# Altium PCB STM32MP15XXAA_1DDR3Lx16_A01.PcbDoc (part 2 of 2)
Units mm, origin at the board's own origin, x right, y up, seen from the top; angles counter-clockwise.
Board outline 86 x 120 mm, 6 copper layers (Top Layer, Signal Layer 1, Signal Layer 2, Signal Layer 3, Signal Layer 4, Bottom Layer), stack 1.556 mm thick; 100 components, 91 nets, 936 pads, 390 vias.
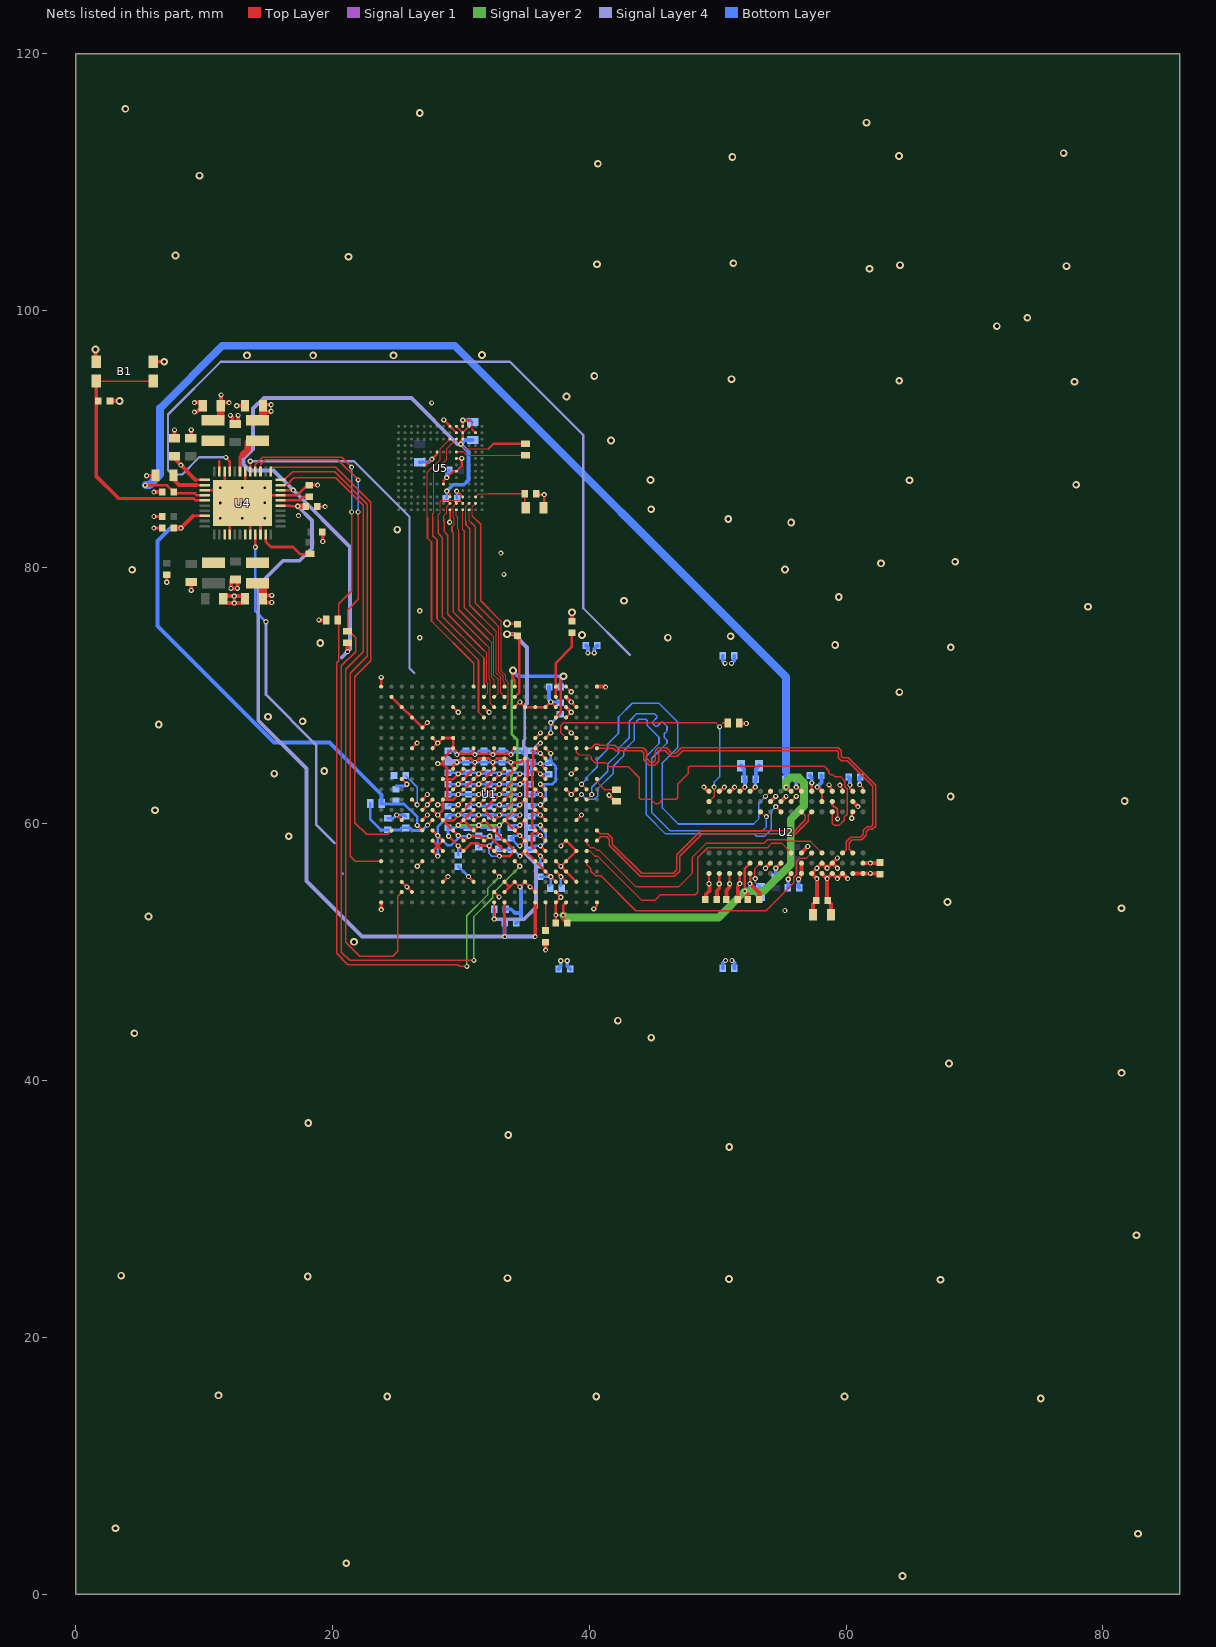
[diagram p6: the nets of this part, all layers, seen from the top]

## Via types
v1: diameter 0.4, hole 0.2, Top Layer to Bottom Layer, tented both sides, 295 vias
v2: diameter 0.6, hole 0.3, Top Layer to Bottom Layer, tented both sides, 93 vias
v3: diameter 0.4, hole 0.2, Top Layer to Signal Layer 1, tented top, 2 vias

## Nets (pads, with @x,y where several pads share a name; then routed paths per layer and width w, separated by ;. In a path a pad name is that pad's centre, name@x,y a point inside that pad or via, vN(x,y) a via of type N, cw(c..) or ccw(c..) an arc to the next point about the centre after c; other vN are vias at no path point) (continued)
DDR_DQ14: U1.U21 U2.H7 | length 21.3
  Top Layer w0.12: U1.U21@39.8,57.9 40.055,57.9 40.45,57.505 40.648,57.505 44.078,54.075 45.135,54.075 45.55,54.49 48.265,54.49 48.455,54.68 48.455,57.385 49.225,58.155 53.88,58.155 54.235,58.51 54.97,58.51 U2.H7@55.73,57.75
DDR_DQ15: U1.V21 U2.F7 | length 22.1
  Top Layer w0.12: U1.V21@39.8,57.1 39.8,56.85 40.12,56.53 40.12,56.327 40.467,55.98 40.893,55.98 43.628,53.245 53.767,53.245 55.935,55.413 55.935,55.846 56.145,56.056 56.145,57.074 56.421,57.35 56.93,57.35 U2.F7@57.33,57.75
DDR_DQM0: U1.G20 U2.D3 | length 31.9
  Top Layer w0.09: 39.184,65.405 39.98,65.405 40.16,65.225
  Top Layer w0.12: U1.G20@39,65.9 39,65.589 39.184,65.405 ; 40.16,65.225 40.16,65.055 40.435,64.78 41.275,64.78 41.585,64.47 43.036,64.47 43.895,63.611 43.895,62.015 43.993,61.917 44.822,61.917 45.154,61.584 45.391,61.584 45.726,61.92 46.77,61.92 46.89,62.04 46.89,63.106 47.715,63.931 47.715,64.41 47.785,64.48 58.336,64.48 58.662,64.154 58.662,63.963 58.805,63.82 58.996,63.82 59.125,63.691 59.572,63.691 59.892,63.372 59.892,62.939 60.09,62.741 60.09,60.765 59.86,60.535 59.86,60.289 59.458,59.888 59.09,59.888 58.93,60.048 U2.D3@58.93,60.95
DDR_DQM1: U1.T21 U2.E7 | length 22.6
  Top Layer w0.12: U1.T21@39.8,58.7 39.8,58.485 40.145,58.14 40.402,58.14 40.597,57.945 40.794,57.945 43.644,55.095 46.962,55.095 48.04,56.174 48.04,57.42 49.135,58.515 53.625,58.515 53.89,58.78 55.325,58.78 55.46,58.645 57.235,58.645 U2.E7@58.13,57.75
DDR_DQS0_N: U1.G21 U2.B7 | length 33.1
  Top Layer w0.1: U1.G21@39.8,65.9 40.162,65.9 40.472,66.21 40.728,66.21 40.808,66.13 41.98,66.13 42.175,65.935 44.19,65.935 44.469,65.656 44.469,65.109 44.758,64.82 45.015,64.82 45.15,64.955 45.15,65.695 45.39,65.935 46.02,65.935 46.435,65.52 46.753,65.52 47.178,65.945 59.39,65.945 59.62,65.715 59.62,65.268 59.731,65.156 60.179,65.156 62.315,63.02 62.315,59.84 62.05,59.575 61.755,59.575 61.593,59.412 61.593,59.117 61.23,58.755 60.47,58.755 60.25,58.535 60.25,58.03 U2.B7@60.53,57.75
DDR_DQS0_P: U1.G22 U2.C7 | length 31.8
  Top Layer w0.1: U1.G22@40.6,65.9 41.751,65.9 ; 41.768,65.9 41.885,65.9 42.08,65.705 44.095,65.705 44.239,65.561 44.239,65.013 44.662,64.59 45.11,64.59 45.405,64.885 45.405,65.575 45.535,65.705 45.925,65.705 46.34,65.29 46.848,65.29 47.273,65.715 59.295,65.715 59.39,65.62 59.39,65.173 59.636,64.926 60.084,64.926 62.085,62.925 62.085,59.935 61.955,59.805 61.66,59.805 61.363,59.508 61.363,59.213 61.135,58.985 60.375,58.985 60.02,58.63 60.02,57.99 U2.C7@59.73,57.7
DDR_DQS1_N: U1.R22 U2.G3 | length 21.1
  Top Layer w0.1: U1.R22@40.6,59.5 40.875,59.225 41.463,59.225 41.795,58.893 41.795,58.429 44.079,56.145 46.527,56.145 46.808,56.426 46.808,57.594 48.7,59.485 56.01,59.485 56.84,60.315 56.84,60.64 U2.G3@56.53,60.95
DDR_DQS1_P: U1.T22 U2.F3 | length 21.4
  Top Layer w0.1: U1.T22@40.6,58.7 40.895,58.995 41.367,58.995 41.565,58.797 41.565,58.334 43.984,55.915 46.622,55.915 47.038,56.331 47.038,57.498 48.795,59.255 56.105,59.255 57.07,60.22 57.07,60.69 U2.F3@57.33,60.95
DDR_ODT: U1.L21 U2.K1 | length 30.7
  Top Layer w0.12: v1(39.4,63.1) U1.L21@39.8,62.7 ; v1(53.73,62.15) U2.K1@54.13,62.55
  Bottom Layer w0.12: v1@39.512,63.1 v1(39.4,63.1) 39.79,63.49 39.79,63.62 40.62,64.45 40.62,65.012 41.45,65.842 41.45,66.229 42.28,67.059 42.28,68.341 43.349,69.41 45.429,69.41 46.89,67.949 46.89,65.959 45.7,64.769 45.7,61.239 46.939,60 52.794,60 53.215,60.421 53.215,61.635 v1(53.73,62.15)
DDR_RASN: U1.M20 U2.J3 | length 31.3
  Top Layer w0.12: U1.M20@39,61.9 v1(39.4,62.3) ; v1(54.53,61.35) U2.J3@54.93,60.95
  Bottom Layer w0.12: v1(39.4,62.3) 39.775,61.925 40.41,61.925 40.65,62.165 40.65,62.719 41.865,63.934 41.865,64.496 42.695,65.326 42.695,65.714 43.525,66.544 43.525,67.825 43.865,68.165 44.4,68.165 44.52,68.045 44.52,67.668 45.435,66.753 45.435,66.265 44.455,65.285 44.455,60.723 45.949,59.229 52.857,59.229 53.044,59.043 53.659,59.043 54.165,59.548 54.165,60.985 v1(54.53,61.35)
DDR_RESETN: R29.2 U1.F19 U2.T2 | length 20.6
  Top Layer w0.12: U1.F19@38.2,66.7 37.799,67.101 37.799,67.694 37.975,67.87 49.88,67.87 v1@50.155,67.595 ; U2.T2@49.33,61.75 49.73,62.15 v1(49.73,62.875) ; v1(50.155,67.565) v1@50.155,67.595 ; R29.2@50.775,67.87 50.42,67.87 50.155,67.605 v1@50.155,67.595
  Bottom Layer w0.12: v1(49.73,62.875) 49.755,62.9 49.755,63.275 50.155,63.675 v1(50.155,67.565)
DDR_WEN: U1.M21 U2.L3 | length 30.4
  Top Layer w0.12: U1.M21@39.8,61.9 v1(40.2,62.3) ; U2.L3@53.33,60.95 v1@53.655,60.625
  Bottom Layer w0.12: v1(40.2,62.3) 40.2,62.856 41.45,64.106 41.45,64.668 42.28,65.498 42.28,65.886 43.11,66.716 43.11,67.997 43.693,68.58 45.085,68.58 45.255,68.41 45.255,68.27 44.935,67.95 44.935,67.84 45.17,67.605 45.305,67.605 45.625,67.925 45.738,67.925 46.06,67.603 46.06,67.245 45.85,67.035 45.85,66.735 46.06,66.525 46.06,66.303 44.87,65.113 44.87,60.895 46.276,59.489 53.519,59.489 53.8,59.77 v1(53.8,60.57)
eMMC_SDIO2_D0: U1.A13 U5.A3 | length 14.9
  Top Layer w0.09: U5.A3@30.65,84.475 30.65,83.634 30.825,83.459 ; 32.739,75.595 32.96,75.374 32.96,71.824 33.295,71.489 33.295,71.14 33.4,71.035 U1.A13@33.4,70.7
  Top Layer w0.13: 30.825,83.459 31.115,83.169 31.115,77.219 32.739,75.595
eMMC_SDIO2_D1: U1.B12 U5.A4 | length 15.9
  Top Layer w0.09: U5.A4@30.15,84.475 30.15,82.932 30.265,82.817 ; 32.356,74.776 32.58,74.552 32.58,71.595 32.905,71.27 32.905,70.185 U1.B12@32.62,69.9
  Top Layer w0.13: 30.265,82.817 30.265,76.867 32.356,74.776 ; U1.B12@32.6,69.965 U1.B12@32.6,69.9 U1.B12@32.62,69.9
eMMC_SDIO2_D2: U1.A12 U5.A5 | length 15
  Top Layer w0.09: U5.A5@29.65,84.475 29.65,84.005 29.775,83.88 29.775,83.005 29.84,82.94 29.84,82.669 ; 32.145,74.385 32.39,74.141 32.39,71.44 32.6,71.23 U1.A12@32.6,70.7
  Top Layer w0.13: 29.84,82.669 29.84,76.691 32.145,74.385
eMMC_SDIO2_D3: U1.C13 U5.B2 | length 17.3
  Top Layer w0.09: 30.9,83.985 30.9,84.725 U5.B2@31.15,84.975 ; 33.015,75.92 33.15,75.785 33.15,71.902 33.485,71.567 33.485,71.219 33.71,70.994 33.71,69.41 U1.C13@33.4,69.1
  Top Layer w0.13: 30.9,83.985 31.54,83.345 31.54,77.395 33.015,75.92
eMMC_SDIO2_D4: U1.B13 U5.B3 | length 16.4
  Top Layer w0.09: 30.4,83.55 30.4,84.725 U5.B3@30.65,84.975 ; 32.584,75.149 32.77,74.963 32.77,71.745 33.095,71.42 33.095,70.205 U1.B13@33.4,69.9
  Top Layer w0.13: 30.4,83.55 30.4,83.283 30.69,82.993 30.69,77.043 32.584,75.149
eMMC_SDIO2_D5: U1.A11 U5.B4 | length 17.9
  Top Layer w0.09: 28.25,83.685 28.25,84.105 28.4,84.255 28.4,85.125 28.5,85.225 29.9,85.225 U5.B4@30.15,84.975
  Top Layer w0.13: 28.25,83.685 28.25,82.633 28.565,82.318 28.565,76.163 31.8,72.928 U1.A11@31.8,70.7
eMMC_SDIO2_D6: U1.C12 U5.B5 | length 17.5
  Top Layer w0.09: 29.31,83.155 29.5,83.345 29.5,83.785 29.4,83.885 29.4,84.725 U5.B5@29.65,84.975 ; 31.96,73.97 32.2,73.73 32.2,71.295 32.295,71.2 32.295,69.405 U1.C12@32.6,69.1
  Top Layer w0.13: 29.31,83.155 29.31,82.775 29.415,82.67 29.415,76.515 31.96,73.97
eMMC_SDIO2_D7: U1.B11 U5.B6 | length 16.8
  Top Layer w0.09: 28.675,83.861 28.675,84.01 28.9,84.235 28.9,84.725 U5.B6@29.15,84.975 ; 31.794,73.534 32.01,73.319 32.01,71.055 32.105,70.96 32.105,70.205 U1.B11@31.8,69.9
  Top Layer w0.13: 28.675,83.861 28.675,83.568 28.703,83.54 28.703,82.781 28.99,82.494 28.99,76.339 31.794,73.534
GND: B1.1 B1.2 C13.1 C14.1 C15.1 C16.1 C17.1 C18.1 C19.1 C20.1 C21.1 C22.2 C23.1 C24.1 C25.1 C26.1 C27.1 C28.1 C29.1 C30.1 C31.1 C32.1 C33.1 C34.1 C35.1 C36.1 C37.1 C38.1 C39.1 C40.1 C41.1 C42.1 C43.1 C44.1 C45.1 C46.1 C47.1 C48.1 C49.1 C50.1 C51.2 C52.1 C53.1 C54.1 C55.1 C56.1 C57.1 C58.1 C59.1 C60.1 C61.1 C62.1 C63.1 C64.1 C65.1 C66.1 C67.1 C68.1 C69.1 C70.1 C71.1 C72.1 C73.1 C74.1 C75.1 C76.1 C79.1 C80.1 C81.1 C82.1 C83.1 C84.1 C85.1 C86.1 C87.1 C90.1 C91.1 C92.1 C93.1 C94.1 C95.1 C96.1 C97.1 R26.1 R27.2 R29.1 R30.1 U1.A1 U1.A19 U1.A22 U1.AA4 U1.AA12 U1.AA13 U1.AA16 U1.AA18 U1.AB1 U1.AB18 U1.AB22 U1.B2 U1.B19 U1.C3 U1.C8 U1.C11 U1.C14 U1.C15 U1.C16 U1.C17 U1.C18 U1.C19 U1.C20 U1.D4 U1.D19 U1.E5 U1.E19 U1.F6 U1.F7 U1.F8 U1.F16 U1.F20 U1.G4 U1.G6 U1.G8 U1.G10 U1.G12 U1.G14 U1.G17 U1.H7 U1.J9 U1.J11 U1.J13 U1.J17 U1.J20 U1.K3 U1.K7 U1.K10 U1.K12 U1.K14 U1.L9 U1.L11 U1.L13 U1.L17 U1.L19 U1.L20 U1.M5 U1.M7 U1.M10 U1.M12 U1.M14 U1.N6 U1.N9 U1.N11 U1.N13 U1.N17 U1.P3 U1.P5 U1.P7 U1.P10 U1.P12 U1.P14 U1.P20 U1.R6 U1.R8 U1.R17 U1.T6 U1.T7 U1.T9 U1.T11 U1.T19 U1.U6 U1.U7 U1.U13 U1.U15 U1.U17 U1.U20 U1.V5 U1.V16 U1.V18 U1.V19 U1.W17 U1.W19 U1.Y3 U1.Y7 U1.Y10 U1.Y13 U1.Y14 U1.Y15 U1.Y18 U1.Y20 U2.A9 U2.B1 U2.B3 U2.B9 U2.D1 U2.D8 U2.E1 U2.E2 U2.E8 U2.F9 U2.G1 U2.G8 U2.G9 U2.J2 U2.J8 U2.M1 U2.M9 U2.P1 U2.P9 U2.T1 U2.T9 U4.6 U4.10 U4.15 U4.26 U4.30 U4.32 U4.41 U4.ep U5.A6 U5.C4 U5.E7 U5.G5 U5.H10 U5.J5 U5.K8 U5.N2 U5.N5 U5.P4 U5.P6 | length 247.4
  Top Layer w0.09: 30.675,91.45 30.9,91.225 30.9,90.725
  Top Layer w0.12: U1.E19@38.2,67.5 v1(38.6,67.1) U1.F20@39,66.7 ; U1.A19@38.2,70.7 v1(38.6,70.3) ; U2.M1@52.53,62.5 U2.M1@52.53,62.55 U2.M1@52.53,62.6
  Top Layer w0.15: U2.T1@49.33,62.5 U2.T1@49.33,62.55
  Top Layer w0.175: B1.1@1.55,96.05 B1.1@1.6,96 B1.1@1.6,96.25 ; C46.1@6.2,87.125 C46.1@6.225,87.15 ; C18.1@8.975,90.05 C18.1@9,90.075 ; C29.1@9.65,92.825 C29.1@9.9,92.575 ; C48.1@11.7,77.75 C48.1@11.5,77.55 11.85,77.2 ; C33.1@12.425,91.15 C33.1@12.65,91.375 ; 12.85,77.2 C38.1@13.2,77.55 C38.1@13,77.75 ; U4.ep@13,85 13.2,85.2 13.6,85.6 U4.41@15.95,85.6 ; C52.1@18.85,84.725 v1(19.425,84.725) ; C51.2@19.2,82.75 C51.2@19.25,82.7 ; U5.H10@27.15,87.975 27.3,87.975 v1(27.75,88.425) 28.15,88.825 U5.K8@28.15,88.975 ; U5.E7@28.65,86.475 28.65,86.725 v1(28.9,86.975) 29.4,87.475 U5.G5@29.65,87.475 30.075,87.9 v1(30.075,88.475) U5.J5@29.65,88.475 ; v1(28.675,91.475) 29.15,91 U5.P6@29.15,90.975 U5.N5@29.65,90.475 ; v1@29.15,83.505 U5.A6@29.15,84.475 ; v1(29.675,85.925) 29.7,85.925 U5.C4@30.15,85.475 ; U5.P4@30.15,90.948 U5.P4@30.15,90.975 v1(30.15,91.45) 30.675,91.45 ; 30.9,90.725 U5.N2@31.15,90.475 ; v1@33.125,81 v1(33.125,81.1) ; C68.1@35.875,85.725 35.95,85.65 v1(36.5,85.65) 36.5,84.675 C69.1@36.45,84.625 ; v1(37.8,58.3) U1.T19@38.2,58.7 ; U1.V19@38.2,57.1 U1.U20@39,57.9 ; U1.D19@38.2,68.3 v1(38.6,68.7) ; v1(38.6,69.5) U1.C20@39,69.1 ; v1(40.35,53.385) 40.6,53.635 U1.AB22@40.6,53.9 ; v1(49.33,55.35) U2.T9@49.33,56.15 ; v1(50.93,55.35) U2.P9@50.93,56.15 ; v1(56.13,62.875) v1@56.205,62.875 ; v1(56.3,55.7) 56.35,55.7 56.48,55.83 56.48,56.1 U2.G9@56.53,56.15 ; U2.E2@58.13,61.75 U2.E1@58.13,62.55 ; v1(58.675,63.045) 58.825,62.895 58.825,62.655 U2.D1@58.93,62.55 ; v1(60.3,63.04) 60.337,63.003 60.337,62.743 U2.B1@60.53,62.55 U2.B1@60.53,62.5 ; v1(60.45,60.45) 60.45,60.87 U2.B3@60.53,60.95
  Top Layer w0.2: U4.15@10.05,86 U4.ep@12,86 ; U4.10@11.6,87.45 11.6,86.4 U4.ep@12,86 ; U4.26@12,82.55 12,84 U4.ep@13,85 ; U4.ep@13.2,85.2 U4.6@13.2,87.45 ; U4.30@13.6,82.55 U4.ep@13.6,84.4 ; U4.32@14.4,82.55 14.4,83.6 U4.ep@13.6,84.4 ; U4.41@15.95,85.6 17.25,85.6 18.05,86.4 C47.1@18.2,86.4 ; U1.A1@23.8,70.7 23.805,70.705 v1(23.805,71.42) ; U1.B2@24.6,69.9 U1.E5@27,67.5 v1(27.4,67.9) ; v1(25,60.7) U1.P3@25.4,60.3 ; U1.Y3@25.4,55.5 v1(25.8,55.1) U1.AA4@26.2,54.7 ; U1.K3@25.4,63.5 v1(25.8,63.1) ; U1.G4@26.2,65.9 v1(26.6,66.3) ; v1@26.61,56.71 U1.V5@27,57.1 ; U1.P5@27,60.3 v1(27.4,60.7) ; U1.M5@27,61.9 v1(27.4,62.3) ; U1.T6@27.8,58.7 28.2,58.3 ; U1.R6@27.8,59.5 v1(28.2,59.1) U1.T7@28.6,58.7 28.2,58.3 ; U1.N6@27.8,61.1 v1(28.2,60.7) ; U1.G6@27.8,65.9 v1(28.2,66.3) ; U1.F6@27.8,66.7 v1(28.2,66.3) ; v1(28.2,57.5) 28.13,57.57 28.065,57.635 U1.U6@27.8,57.9 28.2,58.3 ; v1(28.2,61.5) 28.6,61.5 ; v1(28.2,64.7) 28.225,64.675 28.6,64.675 ; U1.U7@28.6,57.9 28.592,57.907 28.2,58.3 ; U1.M7@28.6,61.9 28.6,61.5 ; U1.K7@28.6,63.475 U1.K7@28.625,63.475 ; U1.Y7@28.6,55.5 v1(29,55.899) ; U1.M7@28.6,61.9 28.625,61.875 29.375,61.875 v1(29.8,62.3) U1.L9@30.2,62.7 v1(31.4,63.9) U1.J11@31.8,64.3 ; U1.K7@28.6,63.5 U1.K7@28.625,63.475 ; 28.935,61.885 28.935,63.475 ; U1.C8@29.4,69.1 v1(29.8,68.7) ; U1.J9@30.2,64.3 v1(29.8,63.9) 29.375,63.475 28.935,63.475 ; v1(30.6,55.9) U1.Y10@31,55.5 ; U1.P10@31,60.3 v1(31.4,60.7) ; U1.G10@31,65.9 31,65.5 v1@31.04,65.46 ; U1.C11@31.8,69.1 v1(32.2,68.7) ; U1.AA12@32.6,54.7 v1(32.98,54.32) ; U1.G12@32.6,65.9 32.6,65.5 v1@32.56,65.46 ; U1.AA13@33.36,54.7 U1.AA13@33.4,54.7 33.8,55.1 ; U1.Y13@33.4,55.5 33.8,55.1 ; U1.U13@33.4,57.9 v1(32.25,59.05) 31.9,58.7 U1.T11@31.8,58.7 31.45,59.05 v1(30.65,59.05) 30.3,58.7 U1.T9@30.2,58.7 v1(29.8,59.1) U1.R8@29.4,59.5 U1.P7@28.625,60.275 ; U1.J13@33.4,64.3 v1(33,63.9) U1.L11@31.8,62.7 v1(31.4,62.3) U1.M10@31,61.9 U1.N9@30.2,61.1 v1(29.8,60.7) 29.8,60.65 29.425,60.275 U1.P7@28.625,60.275 ; v2@33.58,75.61 v2(33.6,75.61) 34.38,75.61 C40.1@34.425,75.565 ; U1.C14@34.19,69.105 34.55,69.465 34.63,69.465 34.995,69.1 U1.C16@35.8,69.1 U1.C17@36.6,69.1 v1(37,69.5) U1.C18@37.4,69.1 ; U1.P14@34.2,60.3 v1(34.6,60.7) ; U1.G14@34.2,65.9 33.9,65.6 v1(33.9,65.4) 33.84,65.46 v1@32.56,65.46 ; v1(34.6,57.5) U1.U15@35,57.9 U1.V16@35.8,57.1 v1(37,55.9) U1.Y18@37.4,55.5 ; v1(34.6,62.3) U1.M14@34.2,61.9 v1(33,60.7) 32.608,60.307 U1.P12@32.6,60.3 U1.N11@31.8,61.1 U1.M12@32.6,61.9 32.61,61.9 32.61,61.91 v1(33,62.3) U1.L13@33.4,62.7 U1.K14@34.2,63.5 v1(34.6,63.9) ; U1.AA16@35.8,54.7 U1.Y15@35,55.5 v1(34.6,55.1) U1.Y14@34.2,55.5 33.8,55.1 ; U1.F16@35.8,66.7 v1(36.2,67.1) ; v1(36.2,58.3) U1.U17@36.6,57.9 ; v1(36.2,59.9) U1.R17@36.6,59.5 ; v1(36.2,61.5) U1.N17@36.6,61.1 ; v1(36.2,63.1) U1.L17@36.6,62.7 ; v1(36.2,64.7) U1.J17@36.6,64.3 ; U1.G17@36.6,65.9 v1(37,65.5) ; C50.1@37.4,52.3 U1.AB18@37.4,53.9 v1(37.8,54.3) U1.AA18@37.4,54.7 ; U1.V18@37.4,57.1 v1(37.8,56.7) ; C50.1@37.445,52.325 C50.1@37.5,52.38 ; U1.W19@38.2,56.3 v1(37.8,56.7) ; U1.V19@38.2,57.1 v1(37.8,56.7) ; U1.T19@38.2,58.7 U1.U20@39,57.9 ; U1.L19@38.2,62.7 v1(38.6,62.3) U1.L20@39,62.7 ; U1.W19@38.2,56.3 U1.Y20@39,55.5 ; v1(38.6,63.9) U1.J20@39,64.3 ; U1.P20@39,60.3 v1(39.4,60.7) ; v1@52.53,55.362 U2.M9@52.53,56.15 ; v1@56.205,62.875 U2.G1@56.53,62.55 ; U4.ep@12,86 U4.ep@13,85 ; U4.ep@13,85 U4.ep@13.6,84.4 ; v1(28.2,60.7) 28.6,61.1 28.6,61.5 ; v1(28.2,60.7) U1.P7@28.625,60.275 ; v1(28.2,66.3) U1.F7@28.6,66.7 U1.F8@29.4,66.7 U1.G8@29.4,65.9 ; 28.6,64.675 U1.H7@28.6,65.1 U1.G8@29.4,65.9 ; 28.6,64.675 28.925,64.35 28.925,63.475 ; U1.K7@28.625,63.475 28.925,63.475 ; 28.925,63.475 28.935,63.475 ; U1.G8@29.4,65.9 29.7,65.6 v1(29.7,65.4) 29.76,65.46 v1@31.04,65.46 ; v1@31.04,65.46 v1(31.1,65.4) 31.16,65.46 32.44,65.46 v1(32.5,65.4) v1@32.56,65.46
  Top Layer w0.25: v3(6.1,83.05) C49.1@6.75,83.05 ; v3(6.1,83.95) C41.1@6.75,83.95 ; v1(7.1,78.825) C32.1@7.1,79.4 ; v1(9,78.2) C39.1@9,78.85 ; C47.1@18.2,86.4 v1(18.85,86.4)
  Top Layer w0.3: B1.1@1.55,96.05 v2(1.55,96.95) ; C44.1@2.675,92.95 v2(3.425,92.95) ; v1(5.525,87.125) C46.1@6.2,87.125 ; B1.2@6.05,96 v2(6.9,96) ; v1(6.1,85.85) C45.1@6.75,85.85 ; C35.1@7.7,90.05 v1(7.7,90.7) ; C18.1@9,90.075 v1(9,90.7) ; v1(9.25,92.075) 9.4,92.075 C29.1@9.9,92.575 ; v1(9.25,92.825) C29.1@9.65,92.825 ; C48.1@11.7,77.75 v1(12.35,77.75) ; 11.85,77.2 v1(12.35,77.2) ; v1(12.05,91.825) 12.225,91.65 C33.1@12.225,91.375 ; C31.1@12.1,79 v1(12.1,78.35) v1(12.6,78.35) 12.6,78.9 C31.1@12.45,79.05 ; v1(12.55,92.575) C34.1@13.2,92.575 ; C33.1@12.65,91.375 v1(12.65,91.825) ; 12.85,77.2 v1(12.35,77.2) ; C38.1@13,77.75 v1(12.35,77.75) ; v1(19.25,82) C51.2@19.25,82.7 ; v1(23.8,53.33) U1.AB1@23.8,53.9 ; v1(36.6,50.18) C42.1@36.6,50.805 ; U1.C19@38.2,69.1 v1(38.6,68.7) ; U1.B19@38.2,69.9 v1(38.6,69.5) ; C43.1@38.655,75.835 v2(38.655,76.485) ; U1.A22@40.6,70.7 41.24,70.7 v1(41.275,70.665) ; v1(41.55,62.235) 42,61.785 R27.2@42.14,61.785 ; v1(48.93,62.875) 49.255,62.55 U2.T1@49.33,62.55 ; C17.1@49.05,54.165 49.1,54.215 49.1,54.526 49.365,54.791 49.365,55.315 v1(49.33,55.35) ; C19.1@50.665,54.12 50.68,54.135 50.68,54.83 50.93,55.08 v1(50.93,55.35) ; U2.P1@50.93,62.55 51.005,62.55 v1(51.33,62.875) ; R29.1@51.675,67.87 51.715,67.83 v1(52.24,67.83) ; v1@52.53,55.362 52.523,55.355 53.253,54.625 53.253,54.123 C25.1@53.25,54.12 ; U2.M1@52.53,62.55 52.605,62.55 v1(52.93,62.875) ; v1(54.53,56.55) U2.J8@54.93,56.95 ; U2.J2@54.93,61.75 v1(55.33,62.15) ; U2.G9@56.53,56.15 U2.G8@56.53,56.95 ; C15.1@57.435,52.94 57.435,53.79 C13.1@57.68,54.035 57.73,54.085 v1(57.73,55.75) U2.F9@57.33,56.15 v1(57.73,56.55) U2.E8@58.13,56.95 v1(58.53,56.55) U2.D8@58.93,56.95 ; v1(57.745,62.875) 57.805,62.875 U2.E1@58.13,62.55 ; v1(59.33,56.55) U2.D8@58.93,56.95 ; v1(59.33,57.35) U2.D8@58.93,56.95 ; U2.B9@60.53,56.15 U2.A9@61.33,56.15 v1(61.9,56.15) 62.595,56.15 C23.1@62.645,56.1 ; v1(12.35,77.2) v1(12.35,77.75)
  Signal Layer 1 w0.2: 20.755,56.158 20.801,56.111
  Bottom Layer w0.12: C92.1@35.425,61.4 C92.1@35.525,61.5
  Bottom Layer w0.175: v1(29.675,85.925) 29.675,85.4 C70.1@29.725,85.35 ; C71.1@30.775,91.45 C71.1@30.925,91.3
  Bottom Layer w0.2: C75.1@24.305,60.435 24.735,60.435 v1(25,60.7) 25.595,60.7 C74.1@25.705,60.59 ; C76.1@24.955,62.96 25.66,62.96 v1(25.8,63.1) ; v1(28.2,57.5) v1(28.2,59.1) ; v1@28.23,57.61 v1@28.31,57.61 ; 28.955,58.335 28.955,58.345 ; C85.1@28.955,60.535 28.2,59.78 v1(28.2,59.1) ; C85.1@29,60.6 29.1,60.7 v1(29.8,60.7) 30.5,60.7 30.6,60.6 30.7,60.7 v1(31.4,60.7) 32.125,60.7 32.225,60.6 32.225,60.65 32.275,60.7 v1(33,60.7) 33.8,60.7 C61.1@33.9,60.6 34,60.7 v1(34.6,60.7) ; C87.1@29,62.3 v1(29.8,62.3) C56.1@30.6,62.3 v1(31.4,62.3) C63.1@32.2,62.3 v1(33,62.3) C62.1@33.8,62.3 v1(34.6,62.3) ; C60.1@29,64 29.7,64 v1(29.8,63.9) 30.2,63.9 30.3,64 C55.1@30.6,64 31.3,64 v1(31.4,63.9) 31.8,63.9 31.9,64 C59.1@32.2,64 32.9,64 v1(33,63.9) 33.7,63.9 C58.1@33.8,64 34.5,64 v1(34.6,63.9) 35.325,63.9 C65.1@35.425,64 35.5,64.075 35.5,64.8 35.6,64.7 v1(36.2,64.7) 36.775,64.7 C97.1@36.85,64.775 37,64.925 v1(37,65.5) ; C64.1@29,65.7 29.4,65.7 v1(29.7,65.4) 29.8,65.4 30.1,65.7 30.8,65.7 v1(31.1,65.4) 31.4,65.7 C67.1@31.8,65.7 32.2,65.7 v1(32.5,65.4) 32.6,65.4 32.9,65.7 C53.1@33.2,65.7 33.6,65.7 v1(33.9,65.4) 34,65.4 34.3,65.7 C66.1@34.6,65.7 C66.1@34.64,65.7 ; v1@29.78,59.085 29.78,58.885 29.24,58.345 28.955,58.345 ; C81.1@29.8,56.7 v1(30.6,55.9) ; v1(29.8,59.1) 29.85,59.05 v1(30.65,59.05) 30.7,59.1 C86.1@31.4,59.1 31.45,59.05 v1(32.25,59.05) ; C80.1@32.925,58 C57.1@33.9,58 34.1,58 v1(34.6,57.5) 35.1,58 35.45,58 35.75,58.3 v1(36.2,58.3) 36.245,58.3 36.6,58.655 36.6,59.285 36.2,59.685 v1(36.2,59.9) ; C66.1@34.62,65.72 C66.1@34.64,65.7 ; C93.1@35.425,59.7 35.625,59.9 v1(36.2,59.9) ; C92.1@35.525,61.5 v1(36.2,61.5) ; C91.1@35.53,64.835 35.505,64.835 C66.1@34.64,65.7 ; C90.1@36.175,55.9 v1(37,55.9) 37,55.3 C96.1@36.9,55.2 ; v1(36.2,63.1) v1@36.29,63.1 ; v1@36.23,61.435 v1@36.255,61.435 ; v1@36.23,61.485 36.6,61.855 36.6,62.79 v1@36.29,63.1 ; v1@36.245,59.9 v1(36.2,59.9) ; C97.1@36.98,64.76 37.13,64.76 37.38,64.51 37.38,63.335 37.145,63.1 v1@36.29,63.1 ; v1(37,69.5) 37.7,69.5 C95.1@37.75,69.45 ; v1(28.2,59.1) 28.955,58.345
  Bottom Layer w0.3: C73.1@26.8,88.175 27.5,88.175 v1(27.75,88.425) ; v1(28.9,86.975) 28.9,87.35 C72.1@29.1,87.55 ; v1(30.15,91.45) C71.1@30.775,91.45 ; C37.1@33.5,53.36 33.93,53.36 34.23,53.06 34.68,53.06 ; C36.1@34.305,52.285 34.68,52.66 34.68,53.06 ; v1(34.6,55.1) 34.68,55.02 34.68,53.06 ; C82.1@36.88,70.66 36.88,69.62 v1(37,69.5) ; v1(38.285,49.35) 38.285,48.95 C30.1@38.52,48.715 ; v1(40.395,73.33) 40.395,73.65 C26.1@40.64,73.895 ; C27.1@50.4,73.1 50.4,72.685 v1(50.58,72.505) ; C28.1@50.405,48.76 50.405,49.16 v1(50.615,49.37) ; v1@52.52,55.355 52.52,55.005 R26.1@53.225,54.3 ; v1(52.93,62.875) 52.93,63.43 C21.1@52.98,63.48 52.98,64.295 C16.1@53.23,64.545 ; v1(54.53,56.55) 54.53,55.915 R30.1@54.56,55.885 ; v1(56.13,62.875) 56.13,63.445 C24.1@56.18,63.495 ; v1(56.3,55.7) 56.3,55.1 C22.2@56.37,55.03 ; v1(57.745,62.875) 57.745,62.89 58.085,63.23 C14.1@58.085,63.775 ; C20.1@60.2,63.65 60.3,63.55 v1(60.3,63.04)
  other v1: 37.405,52.905 55.24,53.265 35.4,55.1 52.52,55.36 26.605,56.71 34.6,69.5 26.805,74.51 26.805,76.61 33.35,79.44 29.13,83.505 11.275,83.8 12.975,83.8 14.725,83.8 17.36,84.02 11.25,85 12.975,85.025 14.725,85.025 11.275,86.2 12.975,86.2 14.725,86.2 27.725,92.8
  other v2: 64.4,1.425 21.075,2.425 82.75,4.725 3.1,5.15 75.165,15.25 24.27,15.415 40.545,15.415 59.88,15.415 11.135,15.5 67.355,24.505 50.885,24.565 33.64,24.63 18.075,24.76 3.545,24.825 82.625,27.975 50.91,34.84 33.7,35.77 18.12,36.705 81.455,40.615 68.03,41.34 44.83,43.36 4.575,43.7 42.23,44.685 21.68,50.82 5.675,52.8 81.455,53.435 67.91,53.92 16.6,59.05 6.175,61.075 81.7,61.785 68.15,62.145 15.475,63.925 19.36,64.12 6.475,67.75 17.68,68.005 14.975,68.35 64.155,70.27 68.155,73.76 59.155,73.935 19.05,74.1 46.125,74.515 51.015,74.62 39.445,74.72 78.85,76.925 42.705,77.385 59.43,77.685 4.4,79.8 55.25,79.825 62.725,80.3 68.5,80.425 25.05,82.925 55.725,83.485 50.83,83.76 44.825,84.515 77.925,86.425 64.95,86.775 44.775,86.8 41.7,89.875 38.225,93.3 77.8,94.45 64.15,94.525 51.075,94.65 40.4,94.9 13.35,96.5 18.5,96.5 24.75,96.5 31.65,96.525 71.75,98.775 74.125,99.425 61.825,103.25 77.175,103.45 64.2,103.525 40.6,103.6 51.225,103.675 21.25,104.175 7.775,104.275 9.65,110.5 40.675,111.425 51.15,111.95 64.125,112.025 76.95,112.25 61.6,114.625 26.8,115.375 3.875,115.7
I2C4_SCL: R37.2 U1.W12 U4.4 | length 66.2
  Top Layer w0.09: 13.975,87.99 13.975,87.475 U4.4@14,87.45
  Top Layer w0.1: 13.975,87.99 14.56,88.575 20.725,88.575 v1(21.5,87.8) v1@21.425,87.8 ; v1(21.5,84.3) 21.5,78.15 20.5,77.15 20.5,72.725 20.325,72.55 20.325,49.915 21.185,49.055 29.765,49.055 29.91,48.91 v1(30.47,48.91)
  Top Layer w0.12: U1.W12@32.6,56.3 v1@32.985,55.915
  Signal Layer 2 w0.12: v1(30.47,48.91) 30.47,52.86 32.11,54.5 32.11,55.01 v1(33,55.9)
  Bottom Layer w0.1: v1(21.5,84.3) v1(21.5,87.8)
I2C4_SDA: R38.2 U1.V14 U4.3 | length 66.8
  Top Layer w0.09: U4.3@14.4,87.45 14.4,88.025
  Top Layer w0.1: 14.4,88.025 14.75,88.375 20.425,88.375 v1(22,86.8) ; v1@22.025,84.275 22.025,77.5 21.175,76.65 R38.2@21.175,75 21.325,75 21.8,74.525 21.8,73.425 20.7,72.325 20.7,50.025 21.345,49.38 v1(31.02,49.38)
  Top Layer w0.12: U1.V14@34.2,57.1 v1(34.595,56.705)
  Signal Layer 2 w0.12: v1(31.02,49.38) 31.02,52.79 32.485,54.255 32.485,54.585 34.595,56.695 v1(34.595,56.705)
  Bottom Layer w0.1: v1(22,84.3) v1(22,86.8)
NetB1_3: B1.3 B1.4 C44.2 U4.17 | length 21.4
  Top Layer w0.1: B1.3@1.325,94.775 B1.3@1.6,94.5 B1.4@6.05,94.5
  Top Layer w0.2: 3.325,85.35 9.2,85.35 9.35,85.2 U4.17@10.05,85.2
  Top Layer w0.3: B1.3@1.6,94.45 1.6,87.1 3.325,85.375
NetC42_2: C42.2 U1.AB17 | length 2.2
  Top Layer w0.12: C42.2@36.6,51.705 U1.AB17@36.6,53.9
NetC43_2: C43.2 U1.A18 U1.B18 | length 5.5
  Top Layer w0.2: U1.B18@37.4,69.9 37.4,72.555 38.655,73.81 C43.2@38.655,74.89
NetC47_2: C47.2 U4.40 | length 2.4
  Top Layer w0.2: U4.40@15.95,85.2 17.45,85.2 17.75,85.5 C47.2@18.2,85.5
NetC68_2: C68.2 C69.2 U5.C2 | length 5.1
  Top Layer w0.09: U5.C2@31.15,85.475 31.4,85.725 32.15,85.725
  Top Layer w0.1: 32.15,85.725 C68.2@34.975,85.725 34.975,84.7 C69.2@35.05,84.625
NetC79_2: C79.2 U1.M4 | length 3.2
  Top Layer w0.13: U1.M4@26.2,61.9 v1(26.6,61.5)
  Bottom Layer w0.13: C79.2@25.695,63.77 26.6,62.865 v1(26.6,61.5)
NetL1_1: L1.1 U4.7 | length 3.2
  Top Layer w0.2: U4.7@12.8,87.45 12.8,88.55 13,88.75
  Top Layer w0.5: 13,88.75 13.4,89.15 13.4,89.75 13.5,89.85 L1.1@14,89.85
NetL2_1: L2.1 U4.11 | length 0.8
  Top Layer w0.2: U4.11@11.2,87.45 11.2,88.25
NetL3_1: L3.1 U4.29
NetL4_1: L4.1 U4.25
NetR26_2: R26.2 U2.L8 | length 2.2
  Top Layer w0.12: v1@52.91,55.75 52.91,56.53 U2.L8@53.33,56.95
  Bottom Layer w0.13: v1(52.93,55.75) 52.93,55.45 53.22,55.16 R26.2@53.325,55.16
NetR27_1: R27.1 U1.K22 | length 2
  Top Layer w0.12: U1.K22@40.6,63.5 40.6,63.265 41.18,62.685 R27.1@42.14,62.685
NetR40_1: R40.1 U5.K5 | length 5.5
  Top Layer w0.09: 30.175,88.975 30.425,88.725 R40.1@35.025,88.725
  Top Layer w0.1: U5.K5@29.65,88.975 30.175,88.975
NetR43_1: R43.1 U4.33 | length 4.4
  Top Layer w0.2: U4.33@14.8,82.55 14.8,82 15.225,81.575 16.925,81.575 17.5,81 R43.1@18.25,81
NRST: U1.R2 U4.1 | length 38.1
  Top Layer w0.09: U4.1@15.2,87.45 U4.1@15.2,87.8
  Top Layer w0.1: U4.1@15.2,87.8 20.275,87.8 23,85.075 23,72.7 21.75,71.45 21.75,60.1 22.66,59.19 24.29,59.19 U1.R2@24.6,59.5
PA0_WKUP: U1.AA3 U4.43 | length 51.5
  Top Layer w0.1: 16.45,86.4 17,86.95 20.275,86.95 22.4,84.825 22.4,73.4 21.05,72.05 21.05,50.79 22.13,49.71 24.7,49.71 25.09,50.1 25.09,54.39 U1.AA3@25.4,54.7
  Top Layer w0.12: U4.43@15.95,86.4 16.45,86.4
PWR_ON: U1.V1 U4.44 | length 38.6
  Top Layer w0.1: U4.44@15.95,86.8 16.25,86.8 16.9,87.45 20.175,87.45 22.725,84.9 22.725,73.05 21.4,71.725 21.4,57.495 21.795,57.1 U1.V1@23.8,57.1
SDMMC2_CK: U1.A10 U5.M6 | length 21.5
  Top Layer w0.09: 27.4,83.9 27.4,87.38 28.4,88.38 28.4,89.225 U5.M6@29.15,89.975
  Top Layer w0.13: 27.4,83.9 27.4,82.281 27.715,81.966 27.715,75.811 31,72.526 U1.A10@31,70.7
SDMMC2_CMD: U1.D11 U5.M5 | length 24.1
  Top Layer w0.09: 27.825,83.9 27.825,84.175 27.9,84.25 27.9,87.4 28.9,88.4 28.9,89.225 U5.M5@29.65,89.975
  Top Layer w0.13: 27.825,83.9 27.825,82.457 28.14,82.142 28.14,75.987 31.38,72.747 31.38,68.72 U1.D11@31.8,68.3
VDD: C38.2 C70.2 C71.2 C80.2 C81.2 C82.2 C83.2 C84.2 C85.2 C86.2 C87.2 L3.2 R37.1 R38.1 R40.2 U1.A14 U1.D18 U1.M6 U1.M9 U1.N5 U1.N8 U1.N10 U1.P9 U1.P11 U1.R10 U1.R12 U1.T13 U1.U9 U1.U12 U1.U14 U4.31 U4.42 U5.C6 U5.M4 U5.N4 U5.P3 U5.P5 | length 142.4
  Top Layer w0.09: v1(30,89.575) 30.35,89.225 32.15,89.225
  Top Layer w0.175: v1(28.9,85.925) 29.15,85.675 U5.C6@29.15,85.475 ; U5.P5@29.65,90.975 U5.N4@30.15,90.475 ; v1(30,89.575) 30,89.825 U5.M4@30.15,89.975 U5.N4@30.15,90.475 ; U5.P3@30.65,90.975 U5.N4@30.15,90.475 ; 32.15,89.225 32.55,89.625 R40.2@35.025,89.625
  Top Layer w0.2: v1(14,81.55) U4.31@14,82.55 ; U4.42@15.95,86 v1(16.95,86) ; U1.N5@27,61.1 v1(27.4,61.5) U1.M6@27.8,61.9 ; v1(29.05,59.05) v1(29.8,58.3) U1.U9@30.2,57.9 30.785,58.485 31.355,58.485 31.53,58.31 v1@32.18,58.31 ; U1.N8@29.4,61.1 v1(29.8,61.5) U1.M9@30.2,61.9 ; v1(29.8,59.9) U1.P9@30.2,60.3 ; U1.N10@31,61.1 U1.P9@30.2,60.3 ; v1(32.2,58.3) U1.U12@32.6,57.9 ; U1.U12@32.665,57.9 U1.U12@32.6,57.9 ; v1(33,59.9) U1.R12@32.6,59.5 ; v2@34.08,71.96 34.08,71.32 34.2,71.2 U1.A14@34.2,70.7 ; U1.U14@34.205,57.96 U1.U14@34.172,57.927 ; U1.D18@37.4,68.3 37.78,68.679 37.78,71.29 v2(38,71.51) ; U1.P9@30.2,60.3 U1.R10@31,59.5 v1(31.4,59.9) U1.P11@31.8,60.3 U1.R12@32.6,59.5 ; U1.U12@32.6,57.9 v1(33,57.5) 33.8,57.5 U1.U14@34.2,57.9 U1.U14@34.172,57.927 ; U1.R12@32.6,59.5 U1.U14@34.172,57.927
  Top Layer w0.3: C38.2@14.65,77.475 14.875,77.25 v1(15.275,77.25) ; C38.2@14.85,77.8 v1(15.275,77.8) ; v1@18.93,75.86 R37.1@19.505,75.86 ; v1(21.175,73.425) R38.1@21.175,74.1 ; v2@34.005,71.96 v2(34.06,71.96) v2@34.08,71.96
  Top Layer w0.6: C38.2@14.6,77.55 L3.2@14.6,78.75
  Signal Layer 2 w0.2: v1(29.8,59.9) v1(31.4,59.9) 32.99,59.9 v1@33.005,59.885 ; v1(33,59.9) 33.93,60.83 33.93,63.96 34.405,64.435 34.405,66.56 33.955,67.01 33.955,71.15 34.06,71.255 v2(34.06,71.96)
  Signal Layer 4 w0.2: v1(14.825,75.75) 14.825,70.07 18.73,66.165 18.73,59.95 20.16,58.52
  Signal Layer 4 w0.3: 20.725,72.975 v1(21.175,73.425) 21.375,73.625 21.375,81.575 v1(16.95,86) 15.425,87.525 13.55,87.525 13.075,88 13.075,88.45 13.825,89.2 13.825,92.35 14.65,93.175 26.15,93.175 29.75,89.575 v1(30,89.575)
  Bottom Layer w0.1: C70.2@28.825,85.35 C70.2@28.9,85.425
  Bottom Layer w0.12: C87.2@29,61.4 C87.2@29.1,61.5
  Bottom Layer w0.13: v1(32.2,58.3) 32.2,57.71 32.41,57.5 v1(33,57.5)
  Bottom Layer w0.175: C70.2@28.9,85.425 v1(28.9,85.925)
  Bottom Layer w0.2: v1(14,81.55) 14,76.575 v1(14.825,75.75) ; v1(29.05,59.05) 29,59.1 C85.2@29,59.7 29.6,59.7 v1(29.8,59.9) 30,59.7 C84.2@30.5,59.7 ; C87.2@29.1,61.5 v1(29.8,61.5) ; C81.2@29.8,57.625 v1(29.8,58.3) ; C84.2@30.6,59.7 30.575,59.675 31.175,59.675 v1(31.4,59.9) 31.6,59.7 C83.2@32.3,59.7 32.8,59.7 v1(33,59.9) 33,58.975 32.925,58.9 32.8,58.9 v1(32.2,58.3) 31.5,58.3 C86.2@31.4,58.2
  Bottom Layer w0.3: v1(28.9,85.925) 29.4,86.425 30.225,86.425 30.6,86.8 30.6,88.975 v1(30,89.575) 30.325,89.9 C71.2@30.925,89.9 ; v2@34.005,71.96 34.455,71.51 v2(38,71.51) ; C82.2@37.78,70.66 37.78,71.29 v2(38,71.51) ; v2@38.08,71.51 v2(38,71.51)
  other v1: 18.95,75.9
VDD_CORE: C34.2 C53.2 C54.2 C55.2 C56.2 C57.2 C58.2 C59.2 C60.2 C61.2 C62.2 C63.2 C64.2 C65.2 C66.2 C67.2 L1.2 U1.H9 U1.H11 U1.H13 U1.H15 U1.J8 U1.J10 U1.J12 U1.J14 U1.K9 U1.K11 U1.K13 U1.K15 U1.L8 U1.L10 U1.L12 U1.L14 U1.M11 U1.M13 U1.M15 U1.N12 U1.N14 U1.P13 U1.P15 U1.R14 U1.T15 U4.5 | length 79.6
  Top Layer w0.15: U4.5@13.6,87.45 v1(13.6,88.25)
  Top Layer w0.175: C34.2@14.6,92.575 C34.2@14.675,92.65 ; U1.N12@32.6,61.1 v1(33,61.5) U1.M13@33.4,61.9 U1.L14@34.2,62.7 v1(34.6,63.1)
  Top Layer w0.2: U1.L8@29.4,62.7 v1(29.8,63.1) U1.K9@30.2,63.5 U1.J10@31,64.3 31,64.425 31.1,64.525 v1(31.1,64.8) ; U1.J8@29.4,64.3 29.4,64.5 v1(29.7,64.8) 30,65.1 30.8,65.1 v1(31.1,64.8) ; U1.L10@31,62.7 v1(31.4,63.1) U1.J12@32.6,64.3 32.6,64.425 32.525,64.5 32.525,64.775 v1(32.5,64.8) ; v1(31.4,61.5) 31.77,61.87 31.77,61.89 32.6,62.72 32.62,62.72 v1(33,63.1) U1.K13@33.4,63.5 U1.J14@34.2,64.3 33.9,64.6 v1(33.9,64.8) ; v1(34.6,58.3) U1.T15@35,58.7 v1(34.6,59.1) U1.R14@34.2,59.5 ; v1(34.6,63.1) U1.K15@34.97,63.47 ; U1.H15@34.94,65.09 34.65,64.8 v1(33.9,64.8) ; U1.M15@34.97,61.89 34.97,61.87 v1(34.585,61.485) U1.N14@34.2,61.1 33.408,60.307 U1.P13@33.4,60.3 U1.R14@34.2,59.5 ; U1.P15@34.99,60.27 34.97,60.27 v1(34.6,59.9) U1.R14@34.2,59.5 ; U1.M15@35,61.9 35,61.955 35.18,62.135 35.18,63.335 U1.K15@35.055,63.46 ; U1.K15@35,63.5 35.205,63.704 35.205,64.91 U1.H15@35.03,65.085 ; v1(31.1,64.8) 31.4,65.1 32.2,65.1 v1(32.5,64.8) ; v1(32.5,64.8) 32.8,65.1 33.6,65.1 v1(33.9,64.8)
  Top Layer w0.3: 14.6,92.1 v1@15.175,92.1 ; C34.2@14.675,92.65 v1(15.225,92.65)
  Top Layer w0.6: L1.2@14,91.45 L1.2@14.15,91.45 14.4,91.45 14.6,91.65 14.6,92.1 C34.2@14.6,92.55
  Signal Layer 4 w0.175: v1(13.6,88.25) 21.675,88.25 26,83.925 26,72.135 26.38,71.755
  Signal Layer 4 w0.5: 29.005,65.06 29.265,64.8 v1(29.7,64.8)
  Bottom Layer w0.175: v1@15.175,92.1 v1(15.225,92.15)
  Bottom Layer w0.2: C60.2@29,63.1 v1(29.8,63.1) C55.2@30.6,63.1 v1(31.4,63.1) C59.2@32.2,63.1 v1(33,63.1) C58.2@33.8,63.1 v1(34.6,63.1) C65.2@35.425,63.1 ; C64.2@29,64.8 v1(29.7,64.8) v1(31.1,64.8) C67.2@31.8,64.8 v1(32.5,64.8) C53.2@33.2,64.8 v1(33.9,64.8) C66.2@34.6,64.8 ; C56.2@30.6,61.4 30.7,61.5 v1(31.4,61.5) 31.5,61.4 C63.2@32.2,61.4 32.3,61.5 v1(33,61.5) 33.1,61.4 C62.2@33.8,61.4 33.885,61.485 v1(34.585,61.485) ; C61.2@33.9,59.7 34.1,59.9 v1(34.6,59.9) ; v1(34.6,58.3) 34.5,58.3 C57.2@33.9,58.9 34.1,59.1 v1(34.6,59.1)
VDD_DDR: C13.2 C14.2 C15.2 C16.2 C17.2 C19.2 C20.2 C21.2 C22.1 C23.2 C26.2 C27.2 C28.2 C29.2 C30.2 C35.2 C90.2 C91.2 C92.2 C93.2 C94.2 C95.2 C96.2 C97.2 L2.2 U1.E18 U1.F17 U1.G16 U1.H17 U1.J16 U1.K17 U1.L16 U1.M17 U1.N16 U1.P17 U1.R16 U1.T17 U1.U16 U1.V17 U1.W18 U1.Y19 U2.A1 U2.A8 U2.B2 U2.C1 U2.C9 U2.D2 U2.D9 U2.E9 U2.F1 U2.G7 U2.H2 U2.H9 U2.K2 U2.K8 U2.N1 U2.N9 U2.R1 U2.R9 U4.9 U4.13 | length 125
  Top Layer w0.12: U1.G16@35.8,65.9 35.82,65.9 U1.G16@35.85,65.9
  Top Layer w0.15: U2.R1@50.13,62.5 U2.R1@50.13,62.55
  Top Layer w0.17: 58.93,61.475 59.08,61.325 59.165,61.325 59.34,61.15 v1@59.34,60.4
  Top Layer w0.175: C35.2@7.7,88.45 C35.2@7.7,88.65 ; C29.2@11.3,92.575 11.325,92.6 C29.2@11.55,92.825 ; v1(37,67.9) U1.E18@37.4,67.5 ; v1(50.13,55.35) U2.R9@50.13,56.15 ; v1(55.5,55.7) 55.62,55.82 55.62,56.04 U2.H9@55.73,56.15 ; U2.H2@55.73,61.75 v1(56.13,62.15) ; 58.93,61.475 58.93,61.723 U2.D2@58.93,61.75 ; v1(59.53,63.025) 59.53,62.951 59.73,62.751 U2.C1@59.73,62.55 ; v1(61.065,63.065) 61.33,62.8 U2.A1@61.33,62.55 ; C23.2@62.595,56.95 C23.2@62.645,57
  Top Layer w0.2: 9.35,86.8 U4.13@10.05,86.8 ; v1(11.7,88.55) 12,88.25 U4.9@12,87.45 ; U1.L16@35.755,62.685 35.755,62.66 35.555,62.46 35.555,61.345 U1.N16@35.8,61.1 U1.N16@35.81,61.09 ; U1.R16@35.78,59.485 35.53,59.235 35.53,58.26 35.8,57.99 U1.U16@35.8,57.9 v1(36.2,57.5) U1.V17@36.6,57.1 ; U1.J16@35.78,64.285 35.58,64.085 35.58,62.885 35.765,62.7 U1.L16@35.8,62.7 v1(36.2,62.3) U1.M17@36.6,61.9 ; U1.N16@35.83,61.11 35.818,61.098 U1.N16@35.81,61.09 ; U1.G16@35.855,65.935 35.82,65.9 U1.G16@35.81,65.89 ; v1(36.2,65.5) U1.H17@36.6,65.1 ; v1(36.2,66.3) U1.G16@35.8,65.9 U1.G16@35.81,65.89 ; v1@36.205,65.46 36.205,65.495 U1.G16@35.81,65.89 ; U1.T17@36.6,58.7 v1(36.2,59.1) U1.R16@35.8,59.5 35.8,59.54 35.555,59.785 35.555,60.835 U1.N16@35.81,61.09 ; U1.P17@36.6,60.3 v1(36.2,60.7) 35.822,61.077 U1.N16@35.81,61.09 ; U1.K17@36.6,63.5 v1(36.2,63.9) 35.8,64.3 35.8,64.315 35.655,64.46 35.655,65.735 U1.G16@35.81,65.89 ; U1.F17@36.6,66.7 v1(37,67.1) ; U1.W18@37.4,56.3 v1(37.8,55.9) U1.Y19@38.2,55.5 ; v1@51.73,55.35 U2.N9@51.73,56.15 ; U2.K8@54.13,56.9 U2.K8@54.13,56.95 ; U2.F1@57.33,62.55 v1(57.33,63.205) ; U2.D2@58.91,61.743 58.93,61.723 U2.D2@58.938,61.714
  Top Layer w0.3: C35.2@7.7,88.45 v1(8.2,87.95) ; v1@8.125,88.025 9.35,86.8 ; C29.2@11.325,92.6 v1(11.325,93.425) ; C29.2@11.55,92.825 v1(11.95,92.825) ; C17.2@49.95,54.12 49.945,54.125 49.945,54.8 50.13,54.985 v1(50.13,55.35) ; U2.R1@50.13,62.5 50.505,62.875 v1(50.53,62.875) ; C19.2@51.565,54.12 51.565,55.185 v1@51.73,55.35 ; U2.N1@51.73,62.55 51.805,62.55 v1(52.13,62.875) ; v1(53.73,56.55) U2.K8@54.13,56.95 ; U2.K2@54.13,61.75 v1(54.53,62.15) ; U2.G7@56.53,57.75 v1(57.025,58.245) ; U2.E9@58.13,56.15 v1(58.53,55.75) ; C15.2@58.835,52.94 58.835,53.78 C13.2@58.58,54.035 58.53,54.085 v1(58.53,55.75) ; v1(60.13,55.75) U2.C9@59.73,56.15 v1(59.33,55.75) U2.D9@58.93,56.15 v1(58.53,55.75) ; U2.B2@60.53,61.75 v1(60.93,61.35) ; U2.A8@61.33,56.95 v1(61.9,56.95) C23.2@62.595,56.95
  Top Layer w0.6: L2.2@10.7,91.45 11.2,91.45 11.3,91.55 C29.2@11.3,92.55
  Signal Layer 4 w0.175: v1@11.692,88.558 9.628,88.558 8.296,87.225 7.55,87.225 7.2,87.575 7.2,91.9 11.3,96 33.825,96 39.53,90.295 39.53,76.805 43.18,73.155
  Bottom Layer w0.12: C94.2@35.425,58.9 C94.2@35.625,59.1 ; C93.2@35.425,60.6 C93.2@35.525,60.7 ; v1@36.175,57.475 v1(36.2,57.5) ; v1(36.2,63.9) v1@36.225,63.875 ; C97.2@36.85,63.9 C97.2@36.875,63.925
  Bottom Layer w0.2: C92.2@35.425,62.3 v1(36.2,62.3) ; C93.2@35.525,60.7 v1(36.2,60.7) ; C94.2@35.625,59.1 v1(36.2,59.1) ; C90.2@36.175,56.8 v1@36.175,57.475 ; v1(36.2,65.5) 35.7,65.5 35.5,65.7 36.1,66.3 v1(36.2,66.3) ; v1@36.225,63.875 C97.2@36.85,63.875 ; v1(37,67.1) 37,67.8 v1@37.09,67.89 ; v1(37,67.9) 37.08,67.9 v1@37.09,67.89 ; C95.2@37.75,68.55 v1@37.09,67.89 ; C96.2@37.8,55.2 v1(37.8,55.9)
  Bottom Layer w0.3: C30.2@37.62,48.715 37.785,48.88 v1(37.785,49.35) ; C26.2@39.74,73.895 39.895,73.74 v1(39.895,73.33) ; v1(51.08,72.505) 51.3,72.725 C27.2@51.3,73.1 ; v1(51.115,49.37) 51.305,49.18 C28.2@51.305,48.76 ; C16.2@51.83,64.545 52.08,64.295 C21.2@52.08,63.48 52.13,63.43 v1(52.13,62.875) ; C22.1@55.47,55.03 C22.1@55.5,55.06 ; v1(55.5,55.7) C22.1@55.5,55.06 ; C22.1@55.525,55.085 C22.1@55.5,55.06 ; C14.2@57.185,63.775 57.33,63.63 v1(57.33,63.205) ; v1(61.065,63.065) 61.065,63.615 C20.2@61.1,63.65
  other v1: 51.73,55.36 59.345,60.4
VDD_USB: C36.2 C52.2 U1.AB13 U1.AB16 U4.39 | length 64
  Top Layer w0.12: v1@33.4,51.245 v1(33.41,51.235) ; v1(35.785,51.23) v1@35.8,51.245
  Top Layer w0.2: U4.39@15.95,84.8 16.75,84.8 16.8,84.75 v1(17.3,84.75)
  Top Layer w0.25: v1@33.4,51.245 U1.AB13@33.4,53.9 ; v1@35.8,51.245 U1.AB16@35.8,53.9
  Top Layer w0.45: v1(17.3,84.75) C52.2@17.85,84.75
  Signal Layer 4 w0.3: v1(17.3,84.75) 18.4,83.65 18.4,81.475 17.428,80.503 16.153,80.503 14.225,78.575 14.225,68.075 17.98,64.32 17.98,55.57 22.315,51.235 v1(33.41,51.235) v1@35.785,51.235
  Bottom Layer w0.3: C36.2@33.405,52.285 33.405,51.26 33.38,51.235 v1@35.8,51.235
VDDA: C49.2 C76.2 R96.1 U1.R5 U4.20 | length 39.7
  Top Layer w0.2: 9.15,84 U4.20@10.05,84 ; v1@26.61,59.889 U1.R5@27,59.5
  Top Layer w0.3: v1(8.2,83.05) 9.15,84
  Top Layer w0.45: C49.2@7.65,83.05 v1(8.2,83.05)
  Bottom Layer w0.2: R96.1@23.83,61.595 23.865,61.56 25.58,61.56 26.61,60.529 v1(26.61,59.895)
  Bottom Layer w0.3: v1(8.2,83.05) 7.375,83.05 6.375,82.05 6.375,75.41 15.45,66.335 19.77,66.335 23.83,62.275 R96.1@23.83,61.595
VDDA_1V8: C37.2 C40.2 U1.AB12 U1.B14 | length 34.3
  Top Layer w0.13: U1.AB12@32.6,53.9 32.6,52.6 v1(32.605,52.595)
  Top Layer w0.2: v2@33.605,74.81 34.205,74.81 34.56,74.455 34.56,70.26 U1.B14@34.2,69.9
  Signal Layer 4 w0.2: 34.905,66.471 34.995,66.562 34.995,69.239
  Signal Layer 4 w0.3: v1@32.605,52.585 34.93,52.585 35.85,53.505 35.85,56.881 35.07,57.661 35.07,65.87 34.905,66.035 34.905,66.471 ; v2@33.58,74.785 v2(33.6,74.785) 34.13,74.785 35.155,73.76 35.155,69.399 35,69.244
  Bottom Layer w0.3: C37.2@32.6,53.36 32.6,52.59 v1@32.605,52.585
VREF+: C74.2 C75.2 R96.2 U1.P6 | length 6.9
  Top Layer w0.2: v1@27.41,59.91 U1.P6@27.8,60.3
  Bottom Layer w0.2: R96.2@22.93,61.595 22.93,60.385 23.78,59.535 C75.2@24.305,59.535 25.205,59.535 25.365,59.695 26.059,59.695 26.259,59.495 26.99,59.495 v1(27.405,59.91)
VREF_DDR: C24.2 C25.2 C45.2 C50.2 U1.AB19 U2.H1 U2.M8 U4.16 | length 115.5
  Top Layer w0.12: v1(55.33,62.875) v1@55.405,62.875
  Top Layer w0.18: v1@52.125,54.76 52.125,56.545 U2.M8@52.53,56.95
  Top Layer w0.2: v1(5.425,86.375) 7.125,86.375 C45.2@7.65,85.85 7.75,85.75 9.3,85.75 9.45,85.6 U4.16@10.05,85.6 ; v1(37.965,52.9) 37.965,53.665 U1.AB19@38.2,53.9 ; v1@55.405,62.875 U2.H1@55.73,62.55
  Top Layer w0.3: v1(37.965,52.9) 37.965,52.615 C50.2@38.28,52.3 ; v1(52.12,54.76) 52.34,54.54 C25.2@52.34,54.115
  Signal Layer 2 w0.6: v1@38.005,52.88 38.165,52.72 50.085,52.72 52.125,54.76 53.605,54.76 55.69,56.845 55.69,60.365 56.73,61.405 56.73,63.22 56.335,63.615 55.655,63.615 55.33,63.29 v1(55.33,62.875)
  Bottom Layer w0.3: v1(55.33,62.875) 55.33,64.085
  Bottom Layer w0.5: v1(5.425,86.375) v1@5.45,86.4
  Bottom Layer w0.6: v1@5.45,86.4 5.755,86.4 6.575,87.22 6.575,92.395 11.435,97.255 29.525,97.255 55.33,71.45 55.33,64.085
VTT_DDR: C46.2 U4.14 | length 3.1
  Top Layer w0.2: 9.4,86.4 U4.14@10.05,86.4
  Top Layer w0.3: C46.2@7.625,87.3 C46.2@7.625,87.15 7.625,86.825 8.05,86.4 9.4,86.4
pads on no net: U1.A2 U1.A3 U1.A4 U1.A5 U1.A6 U1.A7 U1.A8 U1.A9 U1.A15 U1.A16 U1.A17 U1.A20 U1.A21 U1.AA1 U1.AA2 U1.AA5 U1.AA6 U1.AA7 U1.AA8 U1.AA9 U1.AA10 U1.AA11 U1.AA14 U1.AA15 U1.AA17 U1.AA19 U1.AA20 U1.AA21 U1.AA22 U1.AB2 U1.AB3 U1.AB4 U1.AB5 U1.AB6 U1.AB7 U1.AB8 U1.AB9 U1.AB10 U1.AB11 U1.AB14 U1.AB15 U1.AB20 U1.AB21 U1.B1 U1.B3 U1.B4 U1.B5 U1.B6 U1.B7 U1.B8 U1.B9 U1.B10 U1.B15 U1.B16 U1.B17 U1.B20 U1.B21 U1.B22 U1.C1 U1.C2 U1.C4 U1.C5 U1.C6 U1.C7 U1.C9 U1.C10 U1.C21 U1.C22 U1.D1 U1.D2 U1.D3 U1.D5 U1.D6 U1.D7 U1.D8 U1.D9 U1.D10 U1.D12 U1.D13 U1.D14 U1.D15 U1.D16 U1.D17 U1.D20 U1.D21 U1.D22 U1.E1 U1.E2 U1.E3 U1.E4 U1.E6 U1.E7 U1.E8 U1.E9 U1.E10 U1.E11 U1.E12 U1.E13 U1.E14 U1.E15 U1.E16 U1.E17 U1.E22 U1.F1 U1.F2 U1.F3 U1.F4 U1.F5 U1.F9 U1.F10 U1.F11 U1.F12 U1.F13 U1.F14 U1.F15 U1.G1 U1.G2 U1.G3 U1.G5 U1.H1 U1.H2 U1.H3 U1.H4 U1.H5 U1.H6 U1.J1 U1.J2 U1.J3 U1.J4 U1.J5 U1.J6 U1.K1 U1.K2 U1.K4 U1.K5 U1.K6 U1.K21 U1.L1 U1.L2 U1.L3 U1.L4 U1.L5 U1.L6 U1.L22 U1.M1 U1.M2 U1.M3 U1.N1 U1.N2 U1.N3 U1.N4 U1.P1 U1.P2 U1.P4 U1.R1 U1.R3 U1.R4 U1.T1 U1.T2 U1.T3 U1.T4 U1.T5 U1.U1 U1.U2 U1.U3 U1.U4 U1.U5 U1.U8 U1.U10 U1.U11 U1.V2 U1.V3 U1.V4 U1.V6 U1.V7 U1.V8 U1.V9 U1.V10 U1.V11 U1.V12 U1.V13 U1.V15 U1.V22 U1.W1 U1.W2 U1.W3 U1.W4 U1.W5 U1.W6 U1.W7 U1.W8 U1.W9 U1.W10 U1.W11 U1.W13 U1.W14 U1.W15 U1.W16 U1.W20 U1.W21 U1.W22 U1.Y1 U1.Y2 U1.Y4 U1.Y5 U1.Y6 U1.Y8 U1.Y9 U1.Y11 U1.Y12 U1.Y16 U1.Y17 U1.Y21 U1.Y22 U2.J1 U2.J9 U2.L1 U2.L9 U4.2 U4.18 U4.21 U4.23 U4.34 U4.35 U4.38 U5.A1 U5.A2 U5.A7 U5.A8 U5.A9 U5.A10 U5.A11 U5.A12 U5.A13 U5.A14 U5.B1 U5.B7 U5.B8 U5.B9 U5.B10 U5.B11 U5.B12 U5.B13 U5.B14 U5.C1 U5.C3 U5.C5 U5.C7 U5.C8 U5.C9 U5.C10 U5.C11 U5.C12 U5.C13 U5.C14 U5.D1 U5.D2 U5.D3 U5.D4 U5.D12 U5.D13 U5.D14 U5.E1 U5.E2 U5.E3 U5.E5 U5.E8 U5.E9 U5.E10 U5.E12 U5.E13 U5.E14 U5.F1 U5.F2 U5.F3 U5.F10 U5.F12 U5.F13 U5.F14 U5.G1 U5.G2 U5.G3 U5.G10 U5.G12 U5.G13 U5.G14 U5.H1 U5.H2 U5.H3 U5.H5 U5.H12 U5.H13 U5.H14 U5.J1 U5.J2 U5.J3 U5.J12 U5.J13 U5.J14 U5.K1 U5.K2 U5.K3 U5.K6 U5.K7 U5.K10 U5.K12 U5.K13 U5.K14 U5.L1 U5.L2 U5.L3 U5.L12 U5.L13 U5.L14 U5.M1 U5.M2 U5.M3 U5.M7 U5.M8 U5.M9 U5.M10 U5.M11 U5.M12 U5.M13 U5.M14 U5.N1 U5.N3 U5.N6 U5.N7 U5.N8 U5.N9 U5.N10 U5.N11 U5.N12 U5.N13 U5.N14 U5.P1 U5.P2 U5.P7 U5.P8 U5.P9 U5.P10 U5.P11 U5.P12 U5.P13 U5.P14
copper on no net:
  other v2: 41.205,80.305

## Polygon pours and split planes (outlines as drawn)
GND on Bottom Layer "L11-D_GND" (solid, remove dead copper, pour order 140): 0,-0.25 86,-0.25 86,120 0,120
NetL1_1 on Top Layer "NetL1_1" (solid, remove dead copper, pour order 126): 15.05,90.35 13.1,90.35 13.1,89.25 12.7,88.85 12.7,88.55 12.8,88.45 13.2,88.45 14,89.25 14.9,89.25 15.05,89.4
5V_VIN on Top Layer "5V_VIN" (solid, remove dead copper, pour order 128): 11.9,90.05 11.8,89.95 11.8,89.05 12.1,88.75 12.4,88.75 12.9,89.25 12.9,90.05
NetL2_1 on Top Layer "NetL2_1" (solid, remove dead copper, pour order 130): 11.3,88.95 11.3,88.25 11.275,88.225 11.1,88.225 10.775,88.55 10.1,88.55 9.7,88.95 9.7,90.35 9.9,90.55 11.5,90.55 11.7,90.35 11.7,89.35
5V_VIN on Top Layer "NetC47_2" (solid, remove dead copper, pour order 114): 12.7,82.95 12.7,82.05 12.4,81.75 12.4,81.15 12.1,80.85 11.9,80.85 11.8,80.75 11.8,80.25 11.9,80.15 12.8,80.15 12.9,80.25 12.9,80.85 13,80.95 13,82.85 12.9,82.95
NetL3_1 on Top Layer "NetL3_1" (solid, remove dead copper, pour order 122): 13.1,82.95 13.3,82.95 13.3,81.75 13.4,81.65 13.6,81.65 14.2,81.05 14.7,81.05 15.075,80.675 15.075,80.025 14.8,79.75 13.1,79.75 13.1,80.85
NetL4_1 on Top Layer "NetL4_1" (solid, remove dead copper, pour order 124): 11.5,81.65 11.5,82.95 11.7,82.95 11.7,80.05 11.4,79.75 9.9,79.75 9.8,79.85 9.8,80.75 10.1,81.05 10.9,81.05
5V_VIN on Top Layer "5V_VIN" (solid, remove dead copper, pour order 132): 9.5,79.85 8.6,79.85 8.5,79.95 8.5,80.75 9.8,82.05 11,82.05 11.1,82.15 11.1,82.95 11.3,82.95 11.3,81.65 11.2,81.55 10.8,81.15 10,81.15 9.65,80.8 9.65,80.05
5V_VIN on Top Layer "5V_VIN" (solid, remove dead copper, pour order 134): 9.5,89.15 9.4,89.25 8.6,89.25 8.5,89.15 8.5,88.375 9.825,87.05 10.8,87.05 10.9,87.15 10.9,87.95 10.6,88.25 10,88.25 9.5,88.75
GND on Top Layer "GND_L01_P148" (solid, remove dead copper, pour order 148): 0.475,119.601 0.475,0.626 85.73,0.626 85.73,119.601
VDD_CORE on Signal Layer 4 "VDD_CORE" (solid, remove dead copper, pour order 88): 26.225,84.05 20.775,89.5 14.875,89.5 14.875,93 25.775,93 29.375,89.4 31.75,87.024 31.75,70.25 34.79,70.25 34.79,58.75 32.75,58.75 32.75,60 32,60 32,61.25 30.25,61.25 30.25,62.315 26.225,62.315 26.225,68.209
VDD on Signal Layer 4 "VDD" (solid, remove dead copper, pour order 86): 14.237,78.125 20,64.367 20,55.75 33.245,55.75 33.245,60.31 31.75,60.31 31.75,60.986 30,60.986 30,62.25 23.75,62.25 23.75,69.108 17.446,78.125
VDD_DDR on Signal Layer 4 "VDD_DDR" (solid, remove dead copper, pour order 81): 8.2,87.675 7.45,87.967 7.45,91.6 11.625,95.775 33.55,95.775 39,90.325 39,73.65 53.905,73.65 53.905,64.215 62.45,64.215 62.45,51.675 52.65,51.675 52.65,48.25 36.07,48.25 36.07,53.835 35.175,53.835 35.175,67.855 34.45,74.8 34.45,89.525 30.6,93.375 13.075,93.375 10.3,90.6 10.3,89.417
5V_VIN on Signal Layer 4 "5V_VIN" (solid, pour order 136): 8.011,80.816 8,80.828 8,88.55 11.35,88.55 11.359,88.559 11.359,89.316 15.916,89.316 15.925,89.325 15.934,89.316 15.934,83.691 17.998,83.691 18.004,83.686 18,83.682 18,81.575 17.241,80.816
GND on Signal Layer 4 "L11-D_GND" (solid, remove dead copper, pour order 142): 0,120 86,120 86,0 0,0
GND on Signal Layer 1 "GND" (solid, remove dead copper, pour order 96): 0.4,119.595 85.6,119.595 85.6,0.4 0.4,0.4
GND on Signal Layer 2 "GND" (solid, pour order 150): 0,119.985 86,119.985 86,0 0.005,0
GND on Signal Layer 3 "gnd" (solid, pour order 152): 0,120 86,120.005 86,0 0,0

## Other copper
Top Layer:
  pour cut-out: 10.5,87.05 15.5,87.05 15.5,82.95 10.5,82.95
  pour cut-out: 23.305,71.14 27.035,71.14 27.035,84.075 31.535,83.99 33.75,75.505 33.75,71.18 41.48,71.14 41.48,69.13 41.48,68.185 42.47,68.185 42.605,68.185 64.175,68.185 64.175,52.215 63.665,51.86 63.47,51.86 23.305,51.86
Bottom Layer:
  pour cut-out: 36.215,52.761 37.838,49.893 39.426,48.305 51.013,48.305 51.013,50.714 51.013,54.439 56.93,54.439 56.93,62.525 51.433,62.525 51.433,71.128 48.96,73.6 40.9,73.6 36.215,68.915

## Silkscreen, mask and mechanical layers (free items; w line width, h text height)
Bottom Overlay:
  lines w0.2: 30.055,66.915 30.555,66.415 ; 30.555,67.915 30.555,66.415 ; 31.055,66.915 30.555,66.415 ; 18.705,68.15 18.705,83.395 30.2,83.395 30.205,83.39 30.205,68.15 18.705,68.15
M8-Bottom Info:
  lines w0.1: 24.055,68.29 35.155,68.29 35.155,77.39 24.055,77.39 24.055,68.29
  text "ZONE / COMPONENT U11 / PROJECT MB1262A / H : 1mm" at 30.93,77.11 h1 r90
